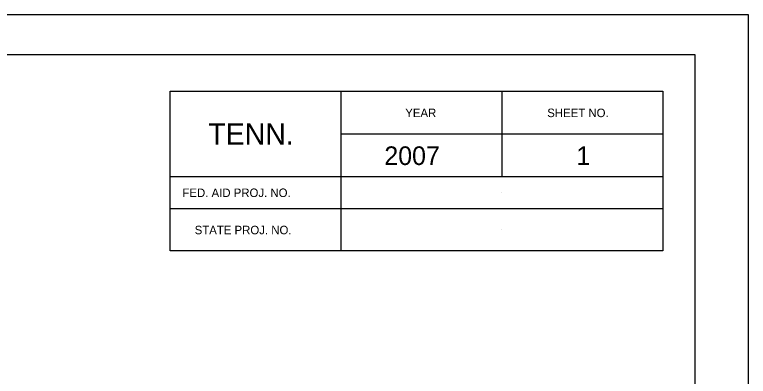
# Model space of a CAD drawing. Extents: x 1623795.1 to 1623879, y 427353.8 to 427391.8.
# Drawn here: x 1623824.18 to 1623831.06, y 427386.46 to 427389.86 of the extents above; entities that cross this region are included whole.
import ezdxf

# ---------------------------------------------------------------- set-up
doc = ezdxf.new("R2010")
doc.units = 0
for name, color, linetype in [('DESIGN - PUBLIC HEARING - Shapes', 7, 'Continuous'), ('DESIGN - SCRATCH - User 1', 7, 'Continuous'), ('DESIGN - SHEET - Corner Text', 7, 'Continuous'), ('DESIGN - SHEET - Light Grid', 7, 'Continuous'), ('DESIGN - SHEET - Linework', 7, 'Continuous')]:
    doc.layers.add(name, color=color, linetype=linetype)

msp = doc.modelspace()

# ---------------------------------------------------------------- linework, layer by layer
at = {"layer": 'DESIGN - PUBLIC HEARING - Shapes'}
msp.add_lwpolyline([(1623799.078, 427389.485), (1623830.562, 427389.485), (1623830.562, 427368.235), (1623799.079, 427368.235)], close=True, dxfattribs=at)
at = {"layer": 'DESIGN - SCRATCH - User 1'}
for p, q in [((1623827.987, 427388.533), (1623827.987, 427388.533)), ((1623828.749, 427388.185), (1623828.749, 427388.185)), ((1623828.749, 427387.838), (1623828.749, 427387.838))]:
    msp.add_line(p, q, dxfattribs=at)
at = {"layer": 'DESIGN - SHEET - Corner Text'}
for p, q in [((1623827.236, 427389.138), (1623827.236, 427387.638)), ((1623828.748, 427389.138), (1623828.748, 427388.338)), ((1623827.236, 427388.737), (1623830.26, 427388.737)), ((1623825.634, 427388.338), (1623830.26, 427388.338)), ((1623825.634, 427388.036), (1623830.26, 427388.036))]:
    msp.add_line(p, q, dxfattribs=at)
msp.add_lwpolyline([(1623825.634, 427387.638), (1623825.634, 427389.138), (1623830.26, 427389.138), (1623830.26, 427387.638)], close=True, dxfattribs=at)
at = {"layer": 'DESIGN - SHEET - Linework'}
for p, q in [((1623795.063, 427389.858), (1623831.063, 427389.858)), ((1623831.063, 427389.858), (1623831.063, 427367.862))]:
    msp.add_line(p, q, dxfattribs=at)
msp.add_lwpolyline([(1623799.078, 427389.485), (1623830.562, 427389.485), (1623830.562, 427368.235), (1623799.079, 427368.235), (1623799.079, 427389.236)], dxfattribs=at)

# ---------------------------------------------------------------- texts
at = {"layer": 'DESIGN - SHEET - Corner Text'}
for s, p in [('2007', (1623827.6459, 427388.445)), ('1', (1623829.449, 427388.445))]:
    msp.add_text(s, height=0.175, dxfattribs=at).set_placement(p)
at = {"layer": 'DESIGN - SHEET - Light Grid'}
for s, height, p in [('YEAR', 0.08, (1623827.842, 427388.895)), ('SHEET NO.', 0.08, (1623829.175, 427388.895)), ('TENN.', 0.2, (1623825.993, 427388.637)), ('FED. AID PROJ. NO.', 0.079998, (1623825.75, 427388.144)), ('STATE PROJ. NO.', 0.079998, (1623825.865, 427387.794))]:
    msp.add_text(s, height=height, dxfattribs=at).set_placement(p)

doc.saveas('drawing.dxf')
